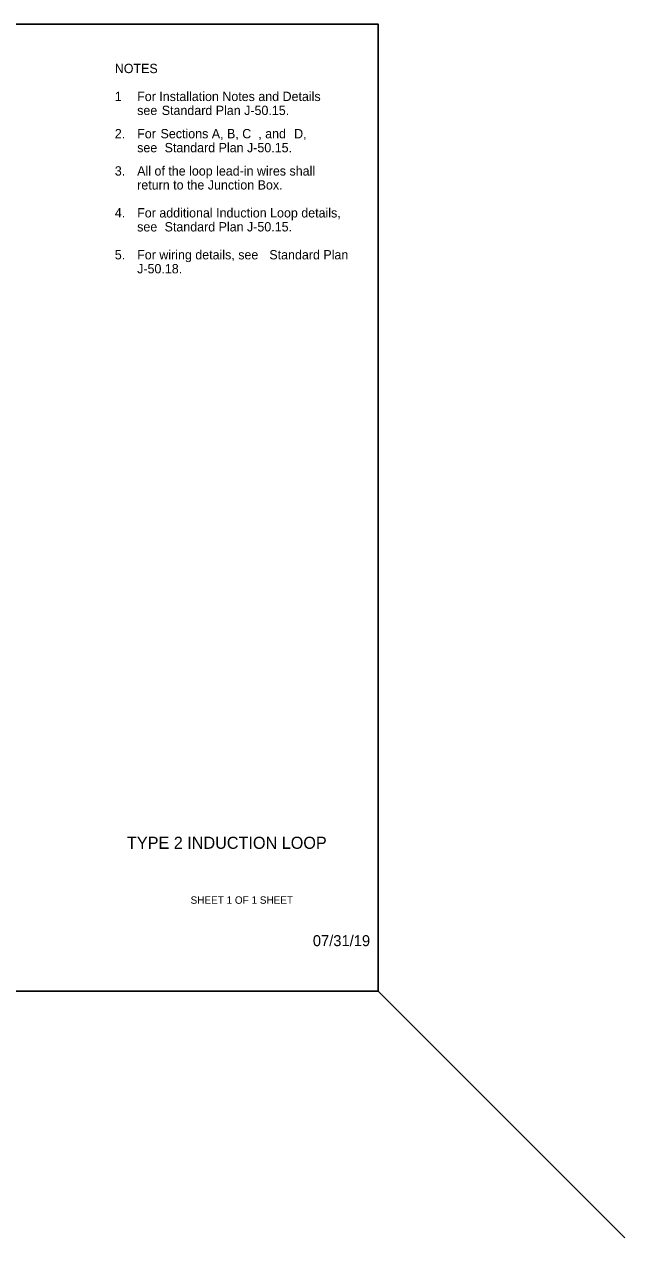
# Model space of a CAD drawing. Extents: x 99862 to 103680, y 99470 to 102076.
# Drawn here: x 102391 to 103680, y 99470 to 102076 of the extents above; entities that cross this region are included whole.
import ezdxf

# ---------------------------------------------------------------- set-up
doc = ezdxf.new("R2010")
doc.units = 0
for name, color, linetype in [('Level 1', 7, 'Continuous'), ('Level 15', 7, 'Continuous'), ('Level 20', 7, 'Continuous'), ('Level 60', 7, 'Continuous'), ('Level 62', 7, 'Continuous')]:
    doc.layers.add(name, color=color, linetype=linetype)

msp = doc.modelspace()

# ---------------------------------------------------------------- linework, layer by layer
at = {"layer": 'Level 1'}
msp.add_line((103150, 100000), (103680.3, 99469.7), dxfattribs=at)
msp.add_lwpolyline([(99862, 99999.5), (103151, 99999.5), (103151, 102075.5), (99862, 102075.5)], close=True, dxfattribs=at)
at = {"layer": 'Level 60'}
msp.add_line((103151, 102075.5), (103151, 102075.5), dxfattribs=at)

# ---------------------------------------------------------------- texts
at = {"layer": 'Level 15'}
msp.add_text('07/31/19', height=23.62, dxfattribs=at).set_placement((103010.7, 100095.8))
at = {"layer": 'Level 20'}
for s, p in [('NOTES', (102585.5, 101970.6)), ('1', (102585.5, 101910.6)), ('For Installation Notes and Details ', (102633.5, 101910.6)), ('see ', (102633.5, 101880.6)), ('Standard Plan J-50.15.', (102686.3, 101880.6)), ('2.', (102585.5, 101830.6)), ('For ', (102633.5, 101830.6)), ('Sections A, B, C', (102683.7, 101830.6)), (', and ', (102893.5, 101830.6)), ('D,', (102970.5, 101830.6)), ('see ', (102633.5, 101800.6)), ('Standard Plan J-50.15.', (102692.4, 101800.6)), ('3.', (102585.5, 101750.6)), ('All of the loop lead-in wires shall ', (102633.5, 101750.6)), ('return to the Junction Box.', (102633.5, 101720.6)), ('4.', (102585.5, 101660.6)), ('For additional Induction Loop details,', (102633.5, 101660.6)), ('see ', (102633.5, 101630.6)), ('Standard Plan J-50.15.', (102692.4, 101630.6)), ('5.', (102585.5, 101570.6)), ('For wiring details, see ', (102633.5, 101570.6)), ('Standard Plan', (102917.3, 101570.6)), ('J-50.18.', (102633.5, 101540.6))]:
    msp.add_text(s, height=20, dxfattribs=at).set_placement(p)
at = {"layer": 'Level 62'}
for s, height, p in [('TYPE 2 INDUCTION LOOP', 26, (102611.6, 100304.8)), ('SHEET 1 OF 1 SHEET', 16, (102748.2, 100186.8))]:
    msp.add_text(s, height=height, dxfattribs=at).set_placement(p)

doc.saveas('drawing.dxf')
